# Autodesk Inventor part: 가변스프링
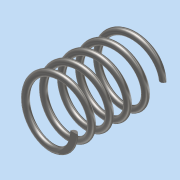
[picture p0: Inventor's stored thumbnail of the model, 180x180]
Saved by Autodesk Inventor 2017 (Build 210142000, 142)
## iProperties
Part Number: 가변스프링
Material: 스테인레스 스틸
Document SubType Name: Modeling
Designer: MRC
Density: 8 g/cm^3
Appearance: 반연마
Mass: 6.99869 g
Surface Area: 17.7558 cm^2
Volume: 0.874837 cm^3
Author: MRC
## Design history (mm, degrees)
sketch "스케치1"
  geometry: L1 (0, 0)-(0, 28.5); L2 (0, 0)-(9, 0); L3 (0, 28.5)-(9, 28.5); C1 r 1 at (9, 0)
  constraints: 6 end point, 2 horizontal, 1 centre point, 1 coincident, 1 parallel, 1 vertical
  dimensions: "d0" = 9 distance of L1.start L2.end; "d1" = 2 diameter of C1; "d4" = 28.5 distance of L1.start L1.end (derived)
feature "코일1" sketch "스케치1" pitch "d5" = 5; turns "d7" = 5; dims "d6" = 28.5 (= d4), "d8" = 0, angle "d9" = 90 deg, angle "d10" = 90 deg, "d11" = 0, "d12" = 0
sketch "스케치2"
  geometry: L1 (0, -12.5)-(28.5, -12.5); L2 (28.5, -12.5)-(28.5, 12.5); L3 (28.5, 12.5)-(0, 12.5); L4 (0, 12.5)-(0, -12.5); 2 further points
  constraints: 8 end point, 2 midpoint, 2 parallel, 1 horizontal, 1 horizontal alignment, 1 perpendicular
  dimensions: "d13" = 25 distance of L1.end L2.end; "d14" = 28.5 distance of L1.start L1.end (= d4)
extrude "돌출1" sketch "스케치2" stored distance "d15" = 25; taper "d16" = 0 deg
node "솔리드1"
